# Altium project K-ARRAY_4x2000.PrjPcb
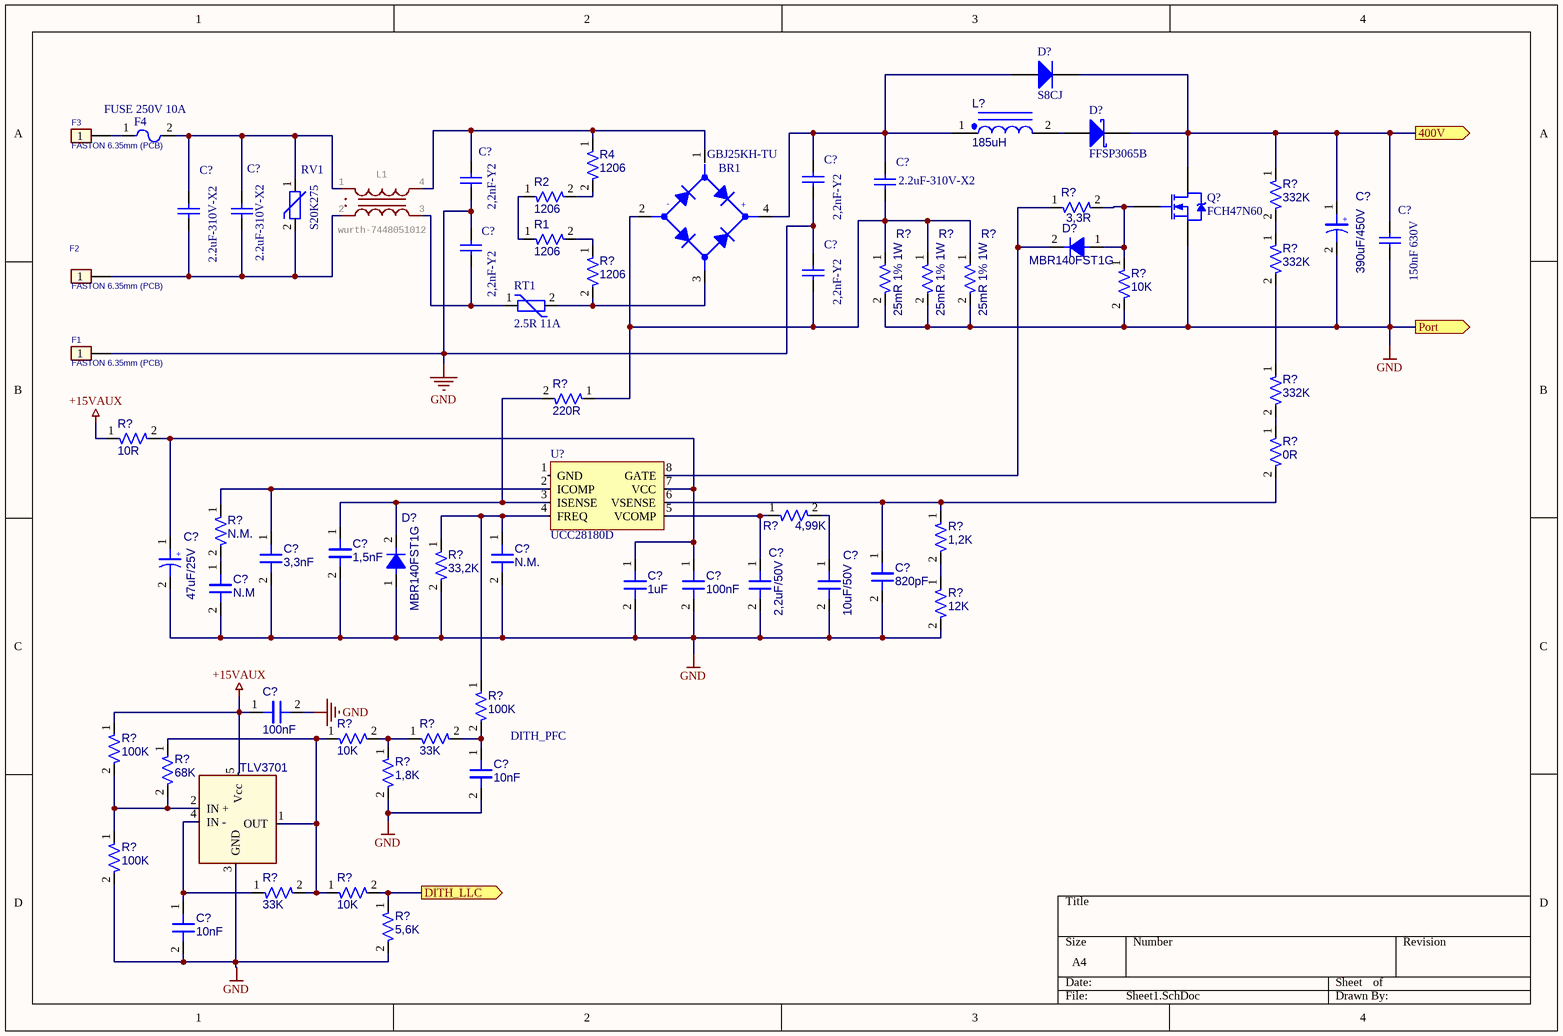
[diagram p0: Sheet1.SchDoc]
1 sheet, 68 parts. Net scope: flat (ports and power ports of the same name join across sheets).

## Sheet Sheet1.SchDoc
size A4; SheetNumber: 1; SheetTotal: 1

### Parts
(Parts that share a designator on the sheet are numbered #1, #2 ... from top to bottom, then left to right.)
BR1  GBJ25KH-TU
C?#1  2.2uF-310V-X2
C?#2  2,2nF-Y2
C?#3  2,2nF-Y2
C?#4  2.2uF-310V-X2
C?#5  2.2uF-310V-X2
C?#6  390uF/450V
C?#7  150nF 630V
C?#8  2,2nF-Y2
C?#9  2,2nF-Y2
C?#10  1,5nF  [0603N_CAP]
C?#11  3,3nF  [0603N_CAP]
C?#12  N.M.  [0603N_CAP]
C?#13  47uF/25V  [ELETTROLITICO_CASE_D]
C?#14  820pF  [0603N_CAP]
C?#15  N.M  [0603N_CAP]
C?#16  1uF  [0603N_CAP]
C?#17  100nF  [0603N_CAP]
C?#18  2,2uF/50V  [1206_UP_CAP]
C?#19  10uF/50V  [1206_UP_CAP]
C?#20  100nF  [0603N_CAP]
C?#21  10nF  [0603N_CAP]
C?#22  10nF  [0603N_CAP]
D?#1  S8CJ  [SMC]
D?#2  FFSP3065B  [TO-220AC]
D?#3  MBR140FST1G
D?#4  MBR140FST1G
F1  FASTON 6.35mm (PCB)  [FASTON_M_PCB_6.35x0.81]
F2  FASTON 6.35mm (PCB)  [FASTON_M_PCB_6.35x0.81]
F3  FASTON 6.35mm (PCB)  [FASTON_M_PCB_6.35x0.81]
F4  FUSE 250V 10A
L1  wurth-7448051012  [WE-CMBNC_XL_7448051012]
L?  185uH
Q?  FCH47N60  [TO-247]
R1  1206  [1206_UP_RES]
R2  1206  [1206_UP_RES]
R4  1206  [1206_UP_RES]
R?#1  332K  [1206_UP_RES]
R?#2  3,3R  [1206_UP_RES]
R?#3  332K  [1206_UP_RES]
R?#4  1206  [1206_UP_RES]
R?#5  25mR 1% 1W  [2512_up]
R?#6  25mR 1% 1W  [2512_up]
R?#7  25mR 1% 1W  [2512_up]
R?#8  10K  [0603N_RES]
R?#9  332K  [1206_UP_RES]
R?#10  220R  [1206_UP_RES]
R?#11  0R  [1206_UP_RES]
R?#12  10R  [1206_UP_RES]
R?#13  N.M.  [0603N_RES]
R?#14  1,2K  [1206_UP_RES]
R?#15  4,99K  [0603N_RES]
R?#16  33,2K  [0603N_RES]
R?#17  12K  [1206_UP_RES]
R?#18  100K  [0603N_RES]
R?#19  100K  [0603N_RES]
R?#20  68K  [0603N_RES]
R?#21  10K  [0603N_RES]
R?#22  33K  [0603N_RES]
R?#23  1,8K  [0603N_RES]
R?#24  100K  [0603N_RES]
R?#25  33K  [0603N_RES]
R?#26  10K  [0603N_RES]
R?#27  5,6K  [0603N_RES]
RT1  2.5R 11A
RV1  S20K275
TLV3701  TLV3701 SOT23-5L  [SOT-23 5PIN]  (value not drawn)
U?  UCC28180D  [SO8]

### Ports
400V (out), DITH_LLC (out), Port (out)

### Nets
+15VAUX: C?#20.1 R?#12.1 R?#19.1 TLV3701.5(Vcc)
GND: C?#2.1 C?#3.1 C?#6.2 C?#7.1 C?#8.2 C?#9.2 C?#10.2 C?#11.2 C?#12.2 C?#13.2 C?#14.2 C?#15.2 C?#16.2 C?#17.2 C?#18.2 C?#19.2 C?#20.2 C?#21.2 C?#22.2 D?#4.1 F1.1 Q?.3(S) R?#5.2 R?#6.2 R?#7.2 R?#8.2 R?#16.2 R?#17.2 R?#23.2 R?#24.2 R?#27.2 TLV3701.3(GND) ; port Port
NetBR1_1: BR1.1(AC1) C?#2.2 L1.4 R4.1
NetBR1_2: BR1.2(-DC) C?#1.2 C?#9.1 R?#5.1 R?#6.1 R?#7.1 R?#10.1
NetBR1_3: BR1.3(AC2) R?#4.2 RT1.2
NetBR1_4: BR1.4(+DC) C?#1.1 C?#3.2 D?#1.1(A) L?.1
NetC?#4_1: C?#4.1 C?#5.1 F4.2 L1.1 RV1.1
NetC?#4_2: C?#4.2 C?#5.2 F2.1 L1.2 RV1.2
NetC?#6_1: C?#6.1 C?#7.2 D?#1.2(K) D?#2.1(K) Q?.2(D) R?#1.1 ; port 400V
NetC?#8_1: C?#8.1 L1.3 RT1.1
NetC?#10_1: C?#10.1 D?#4.2 R?#10.2 U?.3(ISENSE)
NetC?#11_1: C?#11.1 R?#13.1 U?.2(ICOMP)
NetC?#12_1: C?#12.1 R?#16.1 R?#18.1 U?.4(FREQ)
NetC?#13_1: C?#13.1 C?#16.1 C?#17.1 R?#12.2 U?.7(VCC)
NetC?#14_1: C?#14.1 R?#11.2 R?#14.1 U?.6(VSENSE)
NetC?#15_1: C?#15.1 R?#13.2
NetC?#18_1: C?#18.1 R?#15.1 U?.5(VCOMP)
NetC?#19_1: C?#19.1 R?#15.2
NetC?#21_1: C?#21.1 R?#18.2 R?#22.2
NetC?#22_1: C?#22.1 R?#25.1 TLV3701.4(IN_-)
NetD?#2_3: D?#2.3(A) L?.2
NetD?#3_1: D?#3.1 Q?.1(G) R?#2.2 R?#8.1
NetD?#3_2: D?#3.2 R?#2.1 U?.8(GATE)
NetF3_1: F3.1 F4.1
NetR1_1: R1.1 R2.1
NetR1_2: R1.2 R?#4.1
NetR2_2: R2.2 R4.2
NetR?#1_2: R?#1.2 R?#3.1
NetR?#3_2: R?#3.2 R?#9.1
NetR?#9_2: R?#9.2 R?#11.1
NetR?#14_2: R?#14.2 R?#17.1
NetR?#19_2: R?#19.2 R?#20.2 R?#24.1 TLV3701.2(IN_+)
NetR?#20_1: R?#20.1 R?#21.1 R?#25.2 R?#26.1 TLV3701.1(OUT)
NetR?#21_2: R?#21.2 R?#22.1 R?#23.1
NetR?#26_2: R?#26.2 R?#27.1 ; port DITH_LLC

Not connected (* = marked no-connect by the designer): U? 1(GND)

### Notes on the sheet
- DITH_PFC

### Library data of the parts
BR1 = BRIDGE_D15XB60_15A_600V: BRIDGE DIOTEC GBJ25KH-TU 25A 800V; Costo: 0; Aggiornato: NO
C?#1 C?#4 C?#5 = Cap: 2.2uF-310V-X2  VISHAY F339M/52231MIM2T0; Value: 2,2uF
C?#2 C?#3 C?#8 C?#9 = Cap: 2,2nF-Y2-300V MURATA DE6E3KJ222MA4B; Value: 2,2nF
C?#6 = CAP_P_470uF_35V_f3.5_8x20mm_20%: NICHICON LLS2W391MELB 390uF/450V 30x45mm SNAP-IN; Costo: 0,313; Aggiornato: SI; Value: 470u; ContoLavoro: 0
C?#7 = Cap: TDK B32653A6154 150nF 630V MURATA; Value: 2,2nF
C?#10-C?#12 C?#14-C?#17 C?#20-C?#22 = CAP_NP_1nF_50V_5%_0603: 1nF/50V 5% 0603; Aggiornato: S; Costo: 0,01; Value: 1n; ContoLavoro: 0
C?#13 = CAP_P_47uF_50V_CASE_D: 47uF/50V FK SMD CASE D; Aggiornato: SI; Costo: 0,292; Value: 47u; ContoLavoro: 0
C?#18 C?#19 = CAP_NP_10uF_50V_1206_10%: CAP NP 10uF 50V 1206; Costo: 0,15; Aggiornato: S; Value: 10u; ContoLavoro: 0
D?#1 = D_DO-214-AB: VISHAY S8CJ Glass Passivated Rectifier; Aggiornato: NO; Costo: 0
D?#2 = Diode 10TQ035: ONSEMI FFSP3065B Silicon Carbide (SiC) Schottky Diodes; Note: Terminal 2 is the TAB and is electrically connected to the cathode
D?#3 D?#4 = D_LL4148: ON SEMICUNDUCTOR, Schottky Power Rectifier, 1.0 A, 40 V, SOD-123FL; Aggiornato: SI; ContoLavoro: 0
F1-F3 = FASTON_M_PCB_6.35mm: FASTON M PCB 6.35mm; Hpcode: FASTMASCSTAMP; Costo: 0,01; Aggiornato: s; ContoLavoro: 0
F4 = FUSE_250V_6.3A_T_BEL_FUSE_0697A6300-01: PORTAFUIBILE DA C.S.  250Vac 10A 6,3x32; Aggiornato: S; ContoLavoro: 0
L1 = WE-CMBNC_XL_7448051012: GateName_1: G$1; IR: 10A; RDC: 15mOhm; VR: 250  V (AC); VT: 1500  V (AC)
L? = IND_0.49mH_wire Ø1.12mm NO CORE mm. 55(Ø)x36(H): Induttore custom PFC a 4 pin; Costo: 3,598; Value: 0.49m; Aggiornato: SI; Detail: Costo Set crosover già scontato; ContoLavoro: 1
Q? = NMOS-2: FIRECHILD FCH47N60 N-Channel Power MOSFET; Note: Pin 2 is electrically connected to pin 4.
R1 R2 R4 R?#2 R?#4 R?#10-R?#12 R?#14 R?#17 = R_0.33_1%_1206: 1206 SMD RESISTOR; Aggiornato: s; ContoLavoro: 0
R?#1 R?#3 R?#9 = R_0.33_1%_1206: 1206 0,1% SMD RESISTOR; Aggiornato: s; ContoLavoro: 0
R?#5-R?#7 = R_0.5R_1%_2512: 25mOhm 1% 2512 1W WSL SMD RESISTOR; Costo: 0,40; Value: 0,025; Aggiornato: s; ContoLavoro: 0
R?#8 R?#13 R?#15 R?#16 R?#18-R?#27 = R_0R_1%_0603: 0R 1% 0603 SMD RESISTOR; Costo: 0,00073; Value: 0; Aggiornato: S
RT1 = RT_2.5R_10A: NTC 2.5R 11A  TDK B57364S0259M0 21x7; Costo: 0; Aggiornato: NO
RV1 = VARISTOR: VARISTORE TDK S20K275 B72220S0271K101; Aggiornato: NO; ContoLavoro: 0
TLV3701 = TLV3701 SOT23-5L: Costo: 0; DeviceFunction: Voltage Regulator; Aggiornato: NO
U? = UCC28180D: Costo: 1,534; Aggiornato: NO; ContoLavoro: 0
